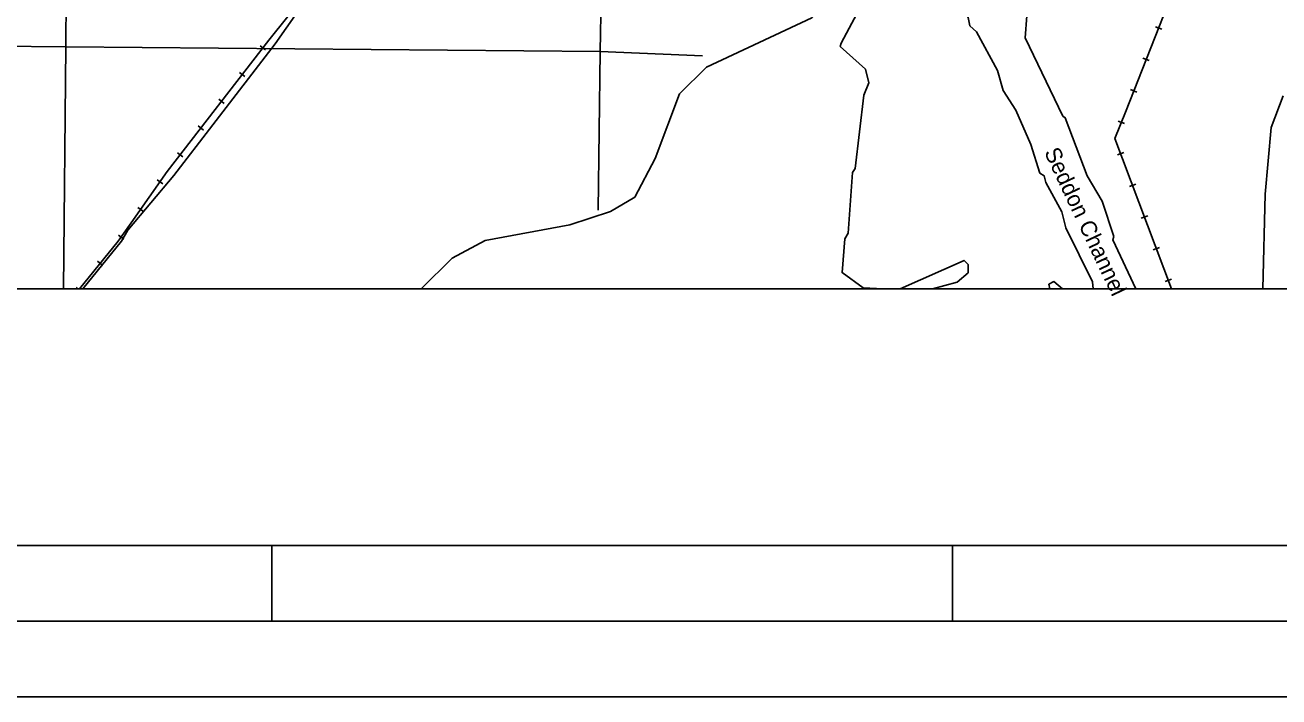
# Model space of a CAD drawing. Extents: x 492225 to 553725, y 1303773 to 1347273.
# Drawn here: x 499152 to 511586, y 1303773 to 1310432 of the extents above; entities that cross this region are included whole.
import ezdxf

# ---------------------------------------------------------------- set-up
doc = ezdxf.new("R2010")
doc.units = 0
for name, color, linetype in [('G-ANNO-TTLB', 7, 'Continuous'), ('Level 1', 7, 'Continuous'), ('Level 22', 7, 'Continuous'), ('Level 37', 7, 'Continuous'), ('Level 41', 7, 'Continuous'), ('Level 5', 7, 'Continuous'), ('Level 52', 7, 'Continuous')]:
    doc.layers.add(name, color=color, linetype=linetype)

msp = doc.modelspace()

# ---------------------------------------------------------------- linework, layer by layer
at = {"layer": 'G-ANNO-TTLB'}
for p, q in [((552225.069, 1305272.564), (494850.069, 1305272.564)), ((501600.069, 1304522.564), (501600.069, 1305272.564)), ((508350.069, 1304522.564), (508350.069, 1305272.564)), ((492975.069, 1304522.564), (552975.069, 1304522.564))]:
    msp.add_line(p, q, dxfattribs=at)
for points in [[(492225.069, 1303772.564), (553725.069, 1303772.564), (553725.069, 1347272.564), (492225.069, 1347272.564)], [(492225.069, 1303772.564), (553725.069, 1303772.564), (553725.069, 1347272.564), (492225.069, 1347272.564)], [(492225.069, 1347272.564), (553725.069, 1347272.564), (553725.069, 1303772.564), (492225.069, 1303772.564)]]:
    msp.add_lwpolyline(points, close=True, dxfattribs=at)
at = {"layer": 'Level 1'}
for p, q in [((499586.966, 1315590.825), (499556.27, 1310217.447)), ((504928.709, 1315540.774), (504856.454, 1310168.978)), ((499556.27, 1310217.447), (495463.793, 1310260.1265)), ((499556.27, 1310217.447), (499534.0534, 1307817.676)), ((504856.454, 1310168.978), (499556.27, 1310217.447)), ((504856.454, 1310168.978), (504835.322, 1308597.987)), ((505870.449, 1310126.507), (504856.454, 1310168.978))]:
    msp.add_line(p, q, dxfattribs=at)
at = {"layer": 'Level 22'}
for p, q in [((502351.784, 1311271.828), (501632.908, 1310247.587)), ((501632.908, 1310247.587), (501012.698, 1309443.283)), ((501012.698, 1309443.283), (500626.798, 1308942.729)), ((500626.798, 1308942.729), (500172.585, 1308399.184)), ((500172.585, 1308399.184), (500107.574, 1308290.374)), ((500107.574, 1308290.374), (499725.2628, 1307817.676))]:
    msp.add_line(p, q, dxfattribs=at)
at = {"layer": 'Level 37'}
for p, q in [((510360.447, 1310415.928), (510423.103, 1310391.249)), ((501535.753, 1310186.618), (501482.424, 1310227.738)), ((510237.727, 1310104.371), (510300.383, 1310079.692)), ((501331.285, 1309921.436), (501277.956, 1309962.557)), ((510115.006, 1309792.813), (510177.663, 1309768.134)), ((501126.817, 1309656.256), (501073.488, 1309697.375)), ((509992.344, 1309481.209), (510055.015, 1309456.57)), ((500922.349, 1309391.074), (500869.02, 1309432.194)), ((500717.881, 1309125.893), (500664.552, 1309167.013)), ((509985.252, 1309144.55), (510048.276, 1309168.276)), ((500518.63, 1308858.691), (500463.559, 1308897.447)), ((510103.223, 1308831.165), (510166.247, 1308854.891)), ((500325.916, 1308584.848), (500270.846, 1308623.605)), ((510221.194, 1308517.78), (510284.218, 1308541.506)), ((500131.84, 1308311.623), (500077.1, 1308350.845)), ((510339.166, 1308204.395), (510402.189, 1308228.121)), ((499922.005, 1308048.18), (499869.714, 1308090.614)), ((510457.137, 1307891.011), (510520.161, 1307914.737)), ((499674.641, 1307817.676), (499658.716, 1307830.599))]:
    msp.add_line(p, q, dxfattribs=at)
for points in [[(511178.402, 1315737.485), (511177.601, 1315519.356), (511176.264, 1315155.806), (511329.151, 1312828.497), (511296.064, 1312610.486), (511198.135, 1312320.001), (511002.542, 1311811.742), (510937.566, 1311702.914), (510807.613, 1311485.259), (510774.923, 1311376.313), (510063.387, 1309569.888), (509960.055, 1309307.057), (510520.7205, 1307817.676)], [(499691.5903, 1307817.676), (500075.284, 1308290.501), (500205.163, 1308471.766), (500562.362, 1308979.338), (501568.472, 1310284.193), (502120.077, 1310972.797)]]:
    msp.add_lwpolyline(points, dxfattribs=at)
at = {"layer": 'Level 5'}
for points in [[(503080.1103, 1307817.676), (503387.645, 1308123.38), (503713.204, 1308297.424), (504555.42, 1308453.263), (504955.869, 1308585.398), (505197.988, 1308726.38), (505399.156, 1309109.154), (505642.764, 1309750.149), (505910.283, 1310016.063), (506953.509, 1310504.655), (507388.096, 1310903.421), (507772.714, 1311318.997), (507890.204, 1311593.658)], [(511697.949, 1311257.264), (511556.44, 1311307.693), (511422.551, 1311133.081), (511305.692, 1311066.72), (511289.791, 1311325.161), (511214.991, 1311392.05), (511059.932, 1311518.059), (510749.703, 1311483.335), (509479.889, 1310872.151), (509187.67, 1310698.018), (509087.15, 1310523.276), (509069.821, 1310306.664), (509442.531, 1309530.435), (509467.471, 1309513.715), (509682.451, 1308937.984), (509682.451, 1308937.984), (509831.731, 1308687.505), (509947.341, 1308337.114), (509938.921, 1308303.804), (510167.4157, 1307817.676)], [(509743.2599, 1307817.676), (509737.633, 1307887.69), (509472.563, 1308421.89), (509431.373, 1308580.371), (509273.873, 1308872.53), (509257.413, 1308939.27), (509215.833, 1308964.39), (509124.983, 1309248.041), (508976.003, 1309590.181), (508851.543, 1309782.23), (508793.833, 1309982.441), (508586.623, 1310366.43), (508520.123, 1310424.99), (508503.693, 1310508.36), (508138.484, 1311009.518), (508038.644, 1311068.158), (507849.757, 1311039.237), (507478.559, 1310696.866), (507244.448, 1310253.757)], [(507485.378, 1309994.668), (507236.018, 1310220.447), (507244.448, 1310253.757)], [(507662.6899, 1307817.676), (507462.211, 1307827.818), (507254.292, 1307978.467), (507280.311, 1308311.768), (507313.831, 1308369.989), (507357.289, 1308969.943), (507382.409, 1309011.523), (507467.938, 1309736.387), (507518.298, 1309861.218), (507485.378, 1309994.668)], [(511425.5246, 1307817.676), (511448.775, 1308757.701), (511509.114, 1309415.904), (511626.723, 1309732.277)], [(508504.437, 1307974.729), (508504.707, 1308058.069), (508463.147, 1308099.869), (507829.2015, 1307817.676)], [(508149.8484, 1307817.676), (508395.818, 1307883.368), (508504.437, 1307974.729)], [(509312.4782, 1307817.676), (509304.204, 1307863.996), (509354.274, 1307888.857), (509440.7316, 1307817.676)]]:
    msp.add_lwpolyline(points, dxfattribs=at)
at = {"layer": 'Level 52'}
msp.add_lwpolyline([(518939.5614, 1342691.8404), (495463.7934, 1342691.8404), (495463.7934, 1307817.676), (518939.5614, 1307817.676)], close=True, dxfattribs=at)

# ---------------------------------------------------------------- texts
at = {"layer": 'Level 41'}
msp.add_text('Seddon Channel', height=159.999996, rotation=295.29717506, dxfattribs=at).set_placement((509254.955, 1309172.513))

doc.saveas('drawing.dxf')
